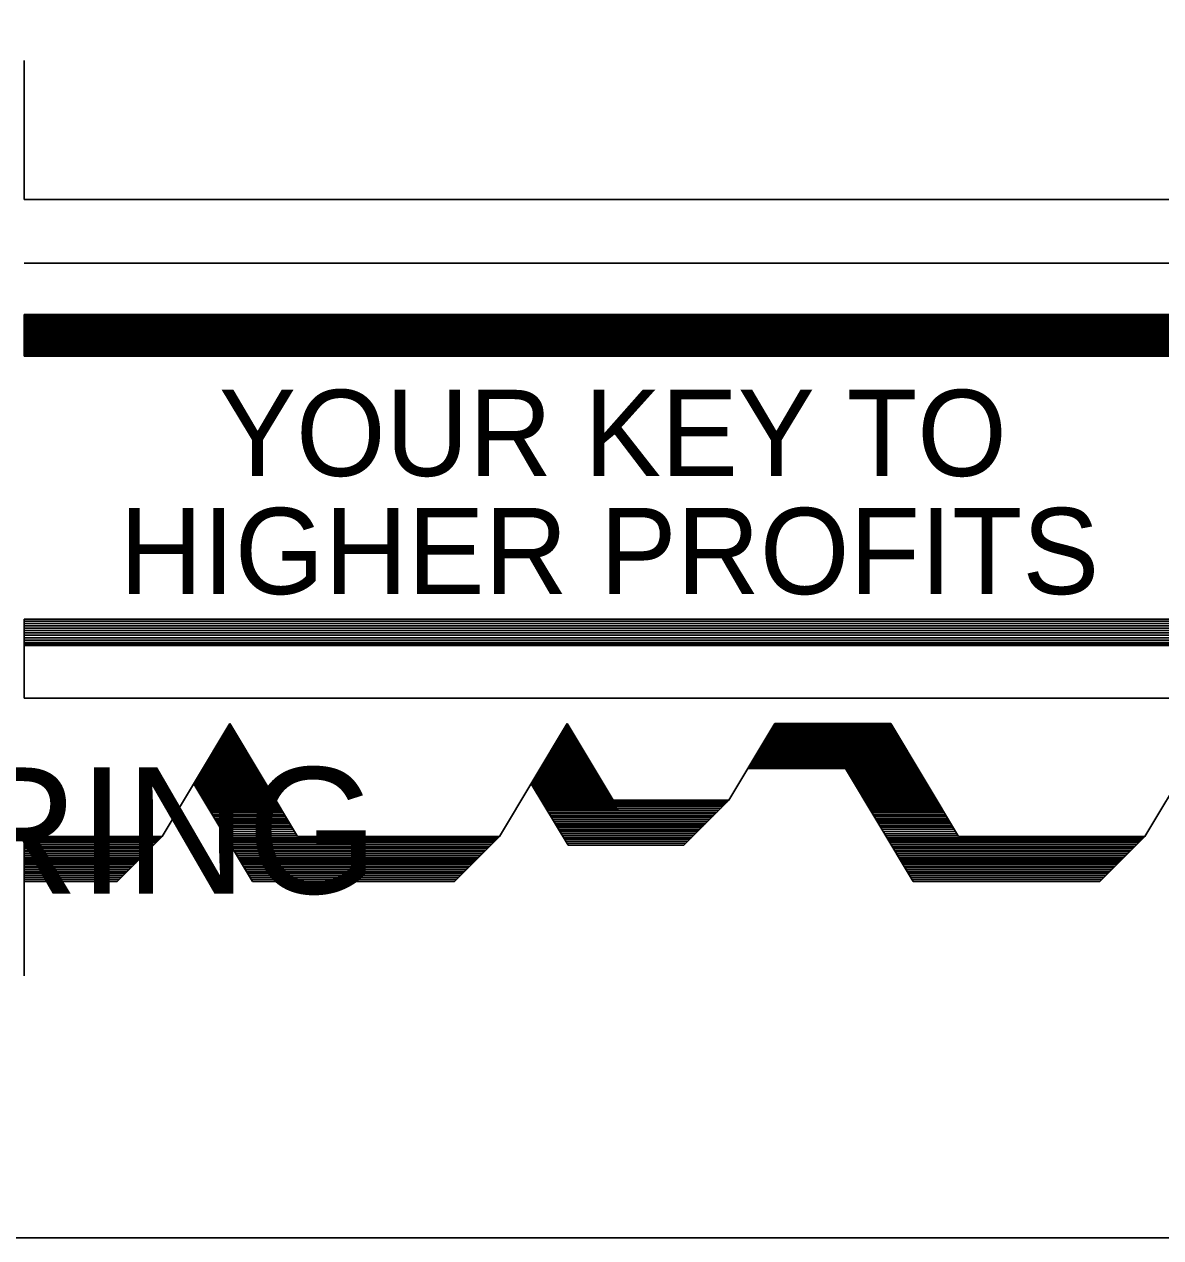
# Model space of a CAD drawing. Extents: x 22371.58 to 22374.41, y 22370.57 to 22372.4.
# Drawn here: x 22371.8644 to 22371.9387, y 22370.6319 to 22370.7113 of the extents above; entities that cross this region are included whole.
import ezdxf

# ---------------------------------------------------------------- set-up
doc = ezdxf.new("R2010")
doc.units = 0
doc.layers.add('G-ANNO-TTBL', color=7, linetype='Continuous')
doc.layers.add('S-SECT-GENF', color=7, linetype='Continuous')

msp = doc.modelspace()

# ---------------------------------------------------------------- linework, layer by layer
at = {"layer": 'G-ANNO-TTBL'}
msp.add_lwpolyline([(22371.776222, 22372.340278), (22374.192888, 22372.340278), (22374.192888, 22370.631945), (22371.776222, 22370.631945)], close=True, dxfattribs=at)
msp.add_lwpolyline([(22371.776222, 22372.340278), (22374.192888, 22372.340278), (22374.192888, 22370.631945), (22371.776222, 22370.631945)], close=True, dxfattribs=at)
at = {"layer": 'S-SECT-GENF'}
for p, q in [((22371.864367, 22370.699874), (22371.864367, 22370.708988)), ((22371.94945, 22370.699874), (22371.864367, 22370.699874)), ((22371.954492, 22370.695707), (22371.864367, 22370.695707)), ((22371.864367, 22370.689634), (22371.864367, 22370.692353)), ((22371.958544, 22370.692353), (22371.864367, 22370.692353)), ((22371.958627, 22370.69229), (22371.864367, 22370.69229)), ((22371.9587, 22370.692228), (22371.864367, 22370.692228)), ((22371.958784, 22370.692155), (22371.864367, 22370.692155)), ((22371.958877, 22370.692082), (22371.864367, 22370.692082)), ((22371.958961, 22370.692009), (22371.864367, 22370.692009)), ((22371.959065, 22370.691926), (22371.864367, 22370.691926)), ((22371.959148, 22370.691853), (22371.864367, 22370.691853)), ((22371.959252, 22370.69177), (22371.864367, 22370.69177)), ((22371.959357, 22370.691686), (22371.864367, 22370.691686)), ((22371.95944, 22370.691613), (22371.864367, 22370.691613)), ((22371.959534, 22370.69153), (22371.864367, 22370.69153)), ((22371.959648, 22370.691447), (22371.864367, 22370.691447)), ((22371.959732, 22370.691374), (22371.864367, 22370.691374)), ((22371.959815, 22370.691301), (22371.864367, 22370.691301)), ((22371.959919, 22370.691218), (22371.864367, 22370.691218)), ((22371.960023, 22370.691134), (22371.864367, 22370.691134)), ((22371.960117, 22370.691051), (22371.864367, 22370.691051)), ((22371.960232, 22370.690957), (22371.864367, 22370.690957)), ((22371.960325, 22370.690884), (22371.864367, 22370.690884)), ((22371.960419, 22370.690801), (22371.864367, 22370.690801)), ((22371.960534, 22370.690707), (22371.864367, 22370.690707)), ((22371.960638, 22370.690624), (22371.864367, 22370.690624)), ((22371.960711, 22370.690561), (22371.864367, 22370.690561)), ((22371.960815, 22370.690478), (22371.864367, 22370.690478)), ((22371.960909, 22370.690395), (22371.864367, 22370.690395)), ((22371.961002, 22370.690322), (22371.864367, 22370.690322)), ((22371.961086, 22370.690249), (22371.864367, 22370.690249)), ((22371.961169, 22370.690186), (22371.864367, 22370.690186)), ((22371.961284, 22370.690093), (22371.864367, 22370.690093)), ((22371.961357, 22370.69003), (22371.864367, 22370.69003)), ((22371.96144, 22370.689957), (22371.864367, 22370.689957)), ((22371.961513, 22370.689895), (22371.864367, 22370.689895)), ((22371.961596, 22370.689832), (22371.864367, 22370.689832)), ((22371.961659, 22370.68978), (22371.864367, 22370.68978)), ((22371.961732, 22370.689718), (22371.864367, 22370.689718)), ((22371.961784, 22370.689676), (22371.864367, 22370.689676)), ((22371.961836, 22370.689634), (22371.864367, 22370.689634)), ((22371.966659, 22370.672426), (22371.864367, 22370.672426)), ((22371.864367, 22370.667259), (22371.864367, 22370.672426)), ((22371.966492, 22370.67229), (22371.864367, 22370.67229)), ((22371.966315, 22370.672145), (22371.864367, 22370.672145)), ((22371.966117, 22370.671978), (22371.864367, 22370.671978)), ((22371.96595, 22370.671843), (22371.864367, 22370.671843)), ((22371.965752, 22370.671676), (22371.864367, 22370.671676)), ((22371.965575, 22370.67153), (22371.864367, 22370.67153)), ((22371.965388, 22370.671374), (22371.864367, 22370.671374)), ((22371.96518, 22370.671207), (22371.864367, 22370.671207)), ((22371.964992, 22370.671051), (22371.864367, 22370.671051)), ((22371.964815, 22370.670905), (22371.864367, 22370.670905)), ((22371.96469, 22370.670801), (22371.864367, 22370.670801)), ((22371.964575, 22370.670707), (22371.864367, 22370.670707)), ((22371.960409, 22370.667259), (22371.864367, 22370.667259)), ((22371.873398, 22370.658207), (22371.877825, 22370.665593)), ((22371.877711, 22370.665405), (22371.87794, 22370.665405)), ((22371.877763, 22370.665488), (22371.877888, 22370.665488)), ((22371.877825, 22370.665593), (22371.882242, 22370.658207)), ((22371.895471, 22370.658207), (22371.899888, 22370.665593)), ((22371.899763, 22370.665384), (22371.900013, 22370.665384)), ((22371.899805, 22370.665447), (22371.899971, 22370.665447)), ((22371.899836, 22370.665509), (22371.89994, 22370.665509)), ((22371.899888, 22370.665593), (22371.902898, 22370.660582)), ((22371.910482, 22370.660582), (22371.913482, 22370.665593)), ((22371.913357, 22370.665384), (22371.92119, 22370.665384)), ((22371.913398, 22370.665457), (22371.921148, 22370.665457)), ((22371.91344, 22370.66552), (22371.921107, 22370.66552)), ((22371.913482, 22370.665593), (22371.921065, 22370.665593)), ((22371.921065, 22370.665593), (22371.925492, 22370.658207)), ((22371.9377, 22370.658207), (22371.942127, 22370.665593)), ((22371.877211, 22370.664572), (22371.87844, 22370.664572)), ((22371.877263, 22370.664655), (22371.878388, 22370.664655)), ((22371.877315, 22370.664738), (22371.878336, 22370.664738)), ((22371.877367, 22370.664822), (22371.878284, 22370.664822)), ((22371.877409, 22370.664905), (22371.878232, 22370.664905)), ((22371.877461, 22370.664988), (22371.87819, 22370.664988)), ((22371.877513, 22370.665072), (22371.878138, 22370.665072)), ((22371.877565, 22370.665155), (22371.878086, 22370.665155)), ((22371.877617, 22370.665238), (22371.878034, 22370.665238)), ((22371.877659, 22370.665322), (22371.877992, 22370.665322)), ((22371.899273, 22370.664572), (22371.900502, 22370.664572)), ((22371.899325, 22370.664655), (22371.90045, 22370.664655)), ((22371.899377, 22370.664738), (22371.900398, 22370.664738)), ((22371.89943, 22370.664822), (22371.900346, 22370.664822)), ((22371.899471, 22370.664905), (22371.900294, 22370.664905)), ((22371.899523, 22370.664988), (22371.900252, 22370.664988)), ((22371.899575, 22370.665072), (22371.9002, 22370.665072)), ((22371.899627, 22370.665155), (22371.900148, 22370.665155)), ((22371.89968, 22370.665238), (22371.900096, 22370.665238)), ((22371.899721, 22370.665322), (22371.900055, 22370.665322)), ((22371.912867, 22370.664572), (22371.92168, 22370.664572)), ((22371.912919, 22370.664655), (22371.921627, 22370.664655)), ((22371.912971, 22370.664738), (22371.921575, 22370.664738)), ((22371.913023, 22370.664822), (22371.921523, 22370.664822)), ((22371.913065, 22370.664905), (22371.921471, 22370.664905)), ((22371.913117, 22370.664988), (22371.92143, 22370.664988)), ((22371.913169, 22370.665072), (22371.921377, 22370.665072)), ((22371.913221, 22370.665155), (22371.921325, 22370.665155)), ((22371.913273, 22370.665238), (22371.921273, 22370.665238)), ((22371.913315, 22370.665311), (22371.921232, 22370.665311)), ((22371.876763, 22370.663822), (22371.878888, 22370.663822)), ((22371.876815, 22370.663905), (22371.878836, 22370.663905)), ((22371.876867, 22370.663988), (22371.878784, 22370.663988)), ((22371.876919, 22370.664072), (22371.878732, 22370.664072)), ((22371.876971, 22370.664155), (22371.87869, 22370.664155)), ((22371.877023, 22370.664238), (22371.878638, 22370.664238)), ((22371.877075, 22370.664322), (22371.878586, 22370.664322)), ((22371.877127, 22370.664405), (22371.878534, 22370.664405)), ((22371.877159, 22370.664488), (22371.878482, 22370.664488)), ((22371.898825, 22370.663822), (22371.90095, 22370.663822)), ((22371.898877, 22370.663905), (22371.900898, 22370.663905)), ((22371.89893, 22370.663988), (22371.900846, 22370.663988)), ((22371.898982, 22370.664072), (22371.900794, 22370.664072)), ((22371.899034, 22370.664155), (22371.900752, 22370.664155)), ((22371.899086, 22370.664238), (22371.9007, 22370.664238)), ((22371.899138, 22370.664322), (22371.900648, 22370.664322)), ((22371.89919, 22370.664405), (22371.900596, 22370.664405)), ((22371.899221, 22370.664488), (22371.900544, 22370.664488)), ((22371.912419, 22370.663822), (22371.922127, 22370.663822)), ((22371.912471, 22370.663905), (22371.922075, 22370.663905)), ((22371.912523, 22370.663988), (22371.922023, 22370.663988)), ((22371.912575, 22370.664072), (22371.921971, 22370.664072)), ((22371.912617, 22370.664155), (22371.92193, 22370.664155)), ((22371.912669, 22370.664238), (22371.921877, 22370.664238)), ((22371.912721, 22370.664322), (22371.921825, 22370.664322)), ((22371.912773, 22370.664405), (22371.921773, 22370.664405)), ((22371.912825, 22370.664488), (22371.921721, 22370.664488)), ((22371.876284, 22370.662988), (22371.879388, 22370.662988)), ((22371.876315, 22370.663072), (22371.879336, 22370.663072)), ((22371.876367, 22370.663155), (22371.879284, 22370.663155)), ((22371.876419, 22370.663238), (22371.879232, 22370.663238)), ((22371.876461, 22370.663322), (22371.87918, 22370.663322)), ((22371.876513, 22370.663405), (22371.879138, 22370.663405)), ((22371.876565, 22370.663488), (22371.879086, 22370.663488)), ((22371.876617, 22370.663572), (22371.879034, 22370.663572)), ((22371.876669, 22370.663655), (22371.878982, 22370.663655)), ((22371.876711, 22370.663738), (22371.87893, 22370.663738)), ((22371.898346, 22370.662988), (22371.90145, 22370.662988)), ((22371.898377, 22370.663072), (22371.901398, 22370.663072)), ((22371.89843, 22370.663155), (22371.901346, 22370.663155)), ((22371.898482, 22370.663238), (22371.901294, 22370.663238)), ((22371.898523, 22370.663322), (22371.901242, 22370.663322)), ((22371.898575, 22370.663405), (22371.9012, 22370.663405)), ((22371.898627, 22370.663488), (22371.901148, 22370.663488)), ((22371.89868, 22370.663572), (22371.901096, 22370.663572)), ((22371.898732, 22370.663655), (22371.901044, 22370.663655)), ((22371.898773, 22370.663738), (22371.900992, 22370.663738)), ((22371.911919, 22370.662988), (22371.922627, 22370.662988)), ((22371.911971, 22370.663072), (22371.922575, 22370.663072)), ((22371.912023, 22370.663155), (22371.922523, 22370.663155)), ((22371.912075, 22370.663238), (22371.922471, 22370.663238)), ((22371.912117, 22370.663322), (22371.922419, 22370.663322)), ((22371.912169, 22370.663405), (22371.922377, 22370.663405)), ((22371.912221, 22370.663488), (22371.922325, 22370.663488)), ((22371.912273, 22370.663572), (22371.922273, 22370.663572)), ((22371.912325, 22370.663655), (22371.922221, 22370.663655)), ((22371.912367, 22370.663738), (22371.922169, 22370.663738)), ((22371.875763, 22370.662155), (22371.879877, 22370.662155)), ((22371.875815, 22370.662238), (22371.879836, 22370.662238)), ((22371.875867, 22370.662322), (22371.879784, 22370.662322)), ((22371.875919, 22370.662405), (22371.879732, 22370.662405)), ((22371.875971, 22370.662488), (22371.87968, 22370.662488)), ((22371.876023, 22370.662572), (22371.879627, 22370.662572)), ((22371.876075, 22370.662655), (22371.879586, 22370.662655)), ((22371.876127, 22370.662738), (22371.879534, 22370.662738)), ((22371.87618, 22370.662822), (22371.879482, 22370.662822)), ((22371.876232, 22370.662905), (22371.87943, 22370.662905)), ((22371.897825, 22370.662155), (22371.90194, 22370.662155)), ((22371.897877, 22370.662238), (22371.901898, 22370.662238)), ((22371.89793, 22370.662322), (22371.901846, 22370.662322)), ((22371.897982, 22370.662405), (22371.901794, 22370.662405)), ((22371.898034, 22370.662488), (22371.901742, 22370.662488)), ((22371.898086, 22370.662572), (22371.90169, 22370.662572)), ((22371.898138, 22370.662655), (22371.901648, 22370.662655)), ((22371.89819, 22370.662738), (22371.901596, 22370.662738)), ((22371.898242, 22370.662822), (22371.901544, 22370.662822)), ((22371.898294, 22370.662905), (22371.901492, 22370.662905)), ((22371.911721, 22370.662655), (22371.922825, 22370.662655)), ((22371.911721, 22370.662645), (22371.918117, 22370.662645)), ((22371.911773, 22370.662738), (22371.922773, 22370.662738)), ((22371.911825, 22370.662822), (22371.922721, 22370.662822)), ((22371.911877, 22370.662905), (22371.922669, 22370.662905)), ((22371.918117, 22370.662645), (22371.922544, 22370.655259)), ((22371.918159, 22370.662572), (22371.922867, 22370.662572)), ((22371.918211, 22370.662488), (22371.922919, 22370.662488)), ((22371.918263, 22370.662405), (22371.922971, 22370.662405)), ((22371.918315, 22370.662322), (22371.923023, 22370.662322)), ((22371.918357, 22370.662238), (22371.923075, 22370.662238)), ((22371.918409, 22370.662155), (22371.923117, 22370.662155)), ((22371.875471, 22370.661655), (22371.879294, 22370.655259)), ((22371.875471, 22370.661655), (22371.88018, 22370.661655)), ((22371.875513, 22370.661738), (22371.880127, 22370.661738)), ((22371.875523, 22370.661572), (22371.880232, 22370.661572)), ((22371.875565, 22370.661822), (22371.880075, 22370.661822)), ((22371.875575, 22370.661488), (22371.880284, 22370.661488)), ((22371.875617, 22370.661905), (22371.880034, 22370.661905)), ((22371.875617, 22370.661405), (22371.880325, 22370.661405)), ((22371.875669, 22370.661988), (22371.879982, 22370.661988)), ((22371.875711, 22370.662072), (22371.87993, 22370.662072)), ((22371.897534, 22370.661655), (22371.89995, 22370.657634)), ((22371.897534, 22370.661655), (22371.902242, 22370.661655)), ((22371.897575, 22370.661738), (22371.90219, 22370.661738)), ((22371.897586, 22370.661572), (22371.902294, 22370.661572)), ((22371.897627, 22370.661822), (22371.902138, 22370.661822)), ((22371.897638, 22370.661488), (22371.902346, 22370.661488)), ((22371.89768, 22370.661905), (22371.902096, 22370.661905)), ((22371.89768, 22370.661405), (22371.902388, 22370.661405)), ((22371.897732, 22370.661988), (22371.902044, 22370.661988)), ((22371.897773, 22370.662072), (22371.901992, 22370.662072)), ((22371.918461, 22370.662072), (22371.923169, 22370.662072)), ((22371.918513, 22370.661988), (22371.923221, 22370.661988)), ((22371.918565, 22370.661905), (22371.923273, 22370.661905)), ((22371.918607, 22370.661822), (22371.923315, 22370.661822)), ((22371.918659, 22370.661738), (22371.923367, 22370.661738)), ((22371.918711, 22370.661655), (22371.923419, 22370.661655)), ((22371.918763, 22370.661572), (22371.923471, 22370.661572)), ((22371.918815, 22370.661488), (22371.923523, 22370.661488)), ((22371.918857, 22370.661405), (22371.923565, 22370.661405)), ((22371.875669, 22370.661322), (22371.880377, 22370.661322)), ((22371.875721, 22370.661238), (22371.880409, 22370.661238)), ((22371.875773, 22370.661155), (22371.880461, 22370.661155)), ((22371.875815, 22370.661072), (22371.880513, 22370.661072)), ((22371.875867, 22370.660988), (22371.880565, 22370.660988)), ((22371.875919, 22370.660905), (22371.880617, 22370.660905)), ((22371.875971, 22370.660822), (22371.880669, 22370.660822)), ((22371.876023, 22370.660738), (22371.880721, 22370.660738)), ((22371.876065, 22370.660655), (22371.880773, 22370.660655)), ((22371.876117, 22370.660572), (22371.880825, 22370.660572)), ((22371.897732, 22370.661322), (22371.90244, 22370.661322)), ((22371.897784, 22370.661238), (22371.902471, 22370.661238)), ((22371.897836, 22370.661155), (22371.902523, 22370.661155)), ((22371.897877, 22370.661072), (22371.902575, 22370.661072)), ((22371.89793, 22370.660988), (22371.902627, 22370.660988)), ((22371.897982, 22370.660905), (22371.90268, 22370.660905)), ((22371.898034, 22370.660822), (22371.902732, 22370.660822)), ((22371.898086, 22370.660738), (22371.902784, 22370.660738)), ((22371.898127, 22370.660655), (22371.902836, 22370.660655)), ((22371.89818, 22370.660572), (22371.902888, 22370.660572)), ((22371.902898, 22370.660582), (22371.910482, 22370.660582)), ((22371.907534, 22370.657634), (22371.910482, 22370.660582)), ((22371.918909, 22370.661322), (22371.923617, 22370.661322)), ((22371.918961, 22370.661238), (22371.923648, 22370.661238)), ((22371.919013, 22370.661155), (22371.9237, 22370.661155)), ((22371.919055, 22370.661072), (22371.923752, 22370.661072)), ((22371.919107, 22370.660988), (22371.923805, 22370.660988)), ((22371.919159, 22370.660905), (22371.923857, 22370.660905)), ((22371.919211, 22370.660822), (22371.923909, 22370.660822)), ((22371.919263, 22370.660738), (22371.923961, 22370.660738)), ((22371.919305, 22370.660655), (22371.924013, 22370.660655)), ((22371.919357, 22370.660572), (22371.924065, 22370.660572)), ((22371.876169, 22370.660488), (22371.880877, 22370.660488)), ((22371.876211, 22370.660426), (22371.880919, 22370.660426)), ((22371.876252, 22370.660343), (22371.880961, 22370.660343)), ((22371.876305, 22370.660259), (22371.881013, 22370.660259)), ((22371.876357, 22370.660165), (22371.881075, 22370.660165)), ((22371.876419, 22370.660061), (22371.881138, 22370.660061)), ((22371.876482, 22370.659968), (22371.88119, 22370.659968)), ((22371.876544, 22370.659853), (22371.881263, 22370.659853)), ((22371.898232, 22370.660488), (22371.90294, 22370.660488)), ((22371.898273, 22370.660426), (22371.902982, 22370.660426)), ((22371.898315, 22370.660343), (22371.903023, 22370.660343)), ((22371.898367, 22370.660259), (22371.903075, 22370.660259)), ((22371.898419, 22370.660165), (22371.903138, 22370.660165)), ((22371.898482, 22370.660061), (22371.9032, 22370.660061)), ((22371.898544, 22370.659968), (22371.903252, 22370.659968)), ((22371.898575, 22370.659926), (22371.909825, 22370.659926)), ((22371.898648, 22370.659801), (22371.9097, 22370.659801)), ((22371.90145, 22370.660478), (22371.910377, 22370.660478)), ((22371.90145, 22370.660384), (22371.910284, 22370.660384)), ((22371.90145, 22370.66029), (22371.91019, 22370.66029)), ((22371.90145, 22370.660176), (22371.910075, 22370.660176)), ((22371.90145, 22370.660061), (22371.909961, 22370.660061)), ((22371.919409, 22370.660488), (22371.924117, 22370.660488)), ((22371.91945, 22370.660426), (22371.924159, 22370.660426)), ((22371.919492, 22370.660343), (22371.9242, 22370.660343)), ((22371.919544, 22370.660259), (22371.924252, 22370.660259)), ((22371.919596, 22370.660165), (22371.924315, 22370.660165)), ((22371.919659, 22370.660061), (22371.924377, 22370.660061)), ((22371.919721, 22370.659968), (22371.92443, 22370.659968)), ((22371.919784, 22370.659853), (22371.924502, 22370.659853)), ((22371.876607, 22370.659749), (22371.881315, 22370.659749)), ((22371.87669, 22370.659624), (22371.881398, 22370.659624)), ((22371.876752, 22370.659509), (22371.881461, 22370.659509)), ((22371.876825, 22370.659384), (22371.881534, 22370.659384)), ((22371.876898, 22370.659259), (22371.881617, 22370.659259)), ((22371.876961, 22370.659155), (22371.88168, 22370.659155)), ((22371.877023, 22370.659051), (22371.881742, 22370.659051)), ((22371.898721, 22370.659676), (22371.909575, 22370.659676)), ((22371.898794, 22370.659561), (22371.909461, 22370.659561)), ((22371.898867, 22370.659436), (22371.909336, 22370.659436)), ((22371.89894, 22370.659311), (22371.909211, 22370.659311)), ((22371.899013, 22370.659186), (22371.909086, 22370.659186)), ((22371.899096, 22370.659061), (22371.908961, 22370.659061)), ((22371.919846, 22370.659749), (22371.924555, 22370.659749)), ((22371.91993, 22370.659624), (22371.924638, 22370.659624)), ((22371.919992, 22370.659509), (22371.9247, 22370.659509)), ((22371.920065, 22370.659384), (22371.924773, 22370.659384)), ((22371.920138, 22370.659259), (22371.924857, 22370.659259)), ((22371.9202, 22370.659155), (22371.924919, 22370.659155)), ((22371.920263, 22370.659051), (22371.924982, 22370.659051)), ((22371.864367, 22370.649093), (22371.864367, 22370.658207)), ((22371.864367, 22370.658207), (22371.873398, 22370.658207)), ((22371.87045, 22370.655259), (22371.873398, 22370.658207)), ((22371.877107, 22370.658926), (22371.881815, 22370.658926)), ((22371.877169, 22370.658811), (22371.881877, 22370.658811)), ((22371.877242, 22370.658686), (22371.88195, 22370.658686)), ((22371.877346, 22370.65852), (22371.882055, 22370.65852)), ((22371.87743, 22370.658384), (22371.882138, 22370.658384)), ((22371.877513, 22370.658238), (22371.882221, 22370.658238)), ((22371.882242, 22370.658207), (22371.895471, 22370.658207)), ((22371.892523, 22370.655259), (22371.895471, 22370.658207)), ((22371.899138, 22370.658978), (22371.908877, 22370.658978)), ((22371.8992, 22370.658884), (22371.908784, 22370.658884)), ((22371.899273, 22370.658759), (22371.908659, 22370.658759)), ((22371.899346, 22370.658634), (22371.908534, 22370.658634)), ((22371.899409, 22370.65853), (22371.90843, 22370.65853)), ((22371.899492, 22370.658395), (22371.908294, 22370.658395)), ((22371.899565, 22370.65827), (22371.908169, 22370.65827)), ((22371.920346, 22370.658926), (22371.925055, 22370.658926)), ((22371.920409, 22370.658811), (22371.925117, 22370.658811)), ((22371.920482, 22370.658686), (22371.92519, 22370.658686)), ((22371.920586, 22370.65852), (22371.925294, 22370.65852)), ((22371.920669, 22370.658384), (22371.925377, 22370.658384)), ((22371.920752, 22370.658238), (22371.925461, 22370.658238)), ((22371.925492, 22370.658207), (22371.9377, 22370.658207)), ((22371.934752, 22370.655259), (22371.9377, 22370.658207)), ((22371.864367, 22370.658103), (22371.873294, 22370.658103)), ((22371.864367, 22370.658009), (22371.8732, 22370.658009)), ((22371.864367, 22370.657915), (22371.873107, 22370.657915)), ((22371.864367, 22370.657801), (22371.872992, 22370.657801)), ((22371.864367, 22370.657686), (22371.872877, 22370.657686)), ((22371.864367, 22370.657551), (22371.872742, 22370.657551)), ((22371.864367, 22370.657426), (22371.872617, 22370.657426)), ((22371.877596, 22370.658103), (22371.895367, 22370.658103)), ((22371.877648, 22370.658009), (22371.895273, 22370.658009)), ((22371.877711, 22370.657915), (22371.89518, 22370.657915)), ((22371.877773, 22370.657801), (22371.895065, 22370.657801)), ((22371.877846, 22370.657686), (22371.89495, 22370.657686)), ((22371.87793, 22370.657551), (22371.894815, 22370.657551)), ((22371.878002, 22370.657426), (22371.89469, 22370.657426)), ((22371.899648, 22370.658145), (22371.908044, 22370.658145)), ((22371.899711, 22370.65803), (22371.90793, 22370.65803)), ((22371.899805, 22370.657884), (22371.907784, 22370.657884)), ((22371.899877, 22370.657759), (22371.907659, 22370.657759)), ((22371.89995, 22370.657634), (22371.907534, 22370.657634)), ((22371.920836, 22370.658103), (22371.937596, 22370.658103)), ((22371.920888, 22370.658009), (22371.937502, 22370.658009)), ((22371.92095, 22370.657915), (22371.937409, 22370.657915)), ((22371.921013, 22370.657801), (22371.937294, 22370.657801)), ((22371.921086, 22370.657686), (22371.93718, 22370.657686)), ((22371.921169, 22370.657551), (22371.937044, 22370.657551)), ((22371.921242, 22370.657426), (22371.936919, 22370.657426)), ((22371.864367, 22370.657301), (22371.872492, 22370.657301)), ((22371.864367, 22370.657186), (22371.872377, 22370.657186)), ((22371.864367, 22370.657061), (22371.872252, 22370.657061)), ((22371.864367, 22370.656936), (22371.872127, 22370.656936)), ((22371.864367, 22370.656811), (22371.872002, 22370.656811)), ((22371.864367, 22370.656686), (22371.871877, 22370.656686)), ((22371.864367, 22370.656603), (22371.871794, 22370.656603)), ((22371.878075, 22370.657301), (22371.894565, 22370.657301)), ((22371.878138, 22370.657186), (22371.89445, 22370.657186)), ((22371.878221, 22370.657061), (22371.894325, 22370.657061)), ((22371.878294, 22370.656936), (22371.8942, 22370.656936)), ((22371.878367, 22370.656811), (22371.894075, 22370.656811)), ((22371.87844, 22370.656686), (22371.89395, 22370.656686)), ((22371.878492, 22370.656603), (22371.893867, 22370.656603)), ((22371.921315, 22370.657301), (22371.936794, 22370.657301)), ((22371.921377, 22370.657186), (22371.93668, 22370.657186)), ((22371.921461, 22370.657061), (22371.936555, 22370.657061)), ((22371.921534, 22370.656936), (22371.93643, 22370.656936)), ((22371.921607, 22370.656811), (22371.936305, 22370.656811)), ((22371.92168, 22370.656686), (22371.93618, 22370.656686)), ((22371.921732, 22370.656603), (22371.936096, 22370.656603)), ((22371.864367, 22370.656509), (22371.8717, 22370.656509)), ((22371.864367, 22370.656384), (22371.871575, 22370.656384)), ((22371.864367, 22370.656259), (22371.87145, 22370.656259)), ((22371.864367, 22370.656155), (22371.871346, 22370.656155)), ((22371.864367, 22370.65602), (22371.871211, 22370.65602)), ((22371.864367, 22370.655895), (22371.871086, 22370.655895)), ((22371.878544, 22370.656509), (22371.893773, 22370.656509)), ((22371.878617, 22370.656384), (22371.893648, 22370.656384)), ((22371.8787, 22370.656259), (22371.893523, 22370.656259)), ((22371.878763, 22370.656155), (22371.893419, 22370.656155)), ((22371.878836, 22370.65602), (22371.893284, 22370.65602)), ((22371.878919, 22370.655895), (22371.893159, 22370.655895)), ((22371.921784, 22370.656509), (22371.936002, 22370.656509)), ((22371.921857, 22370.656384), (22371.935877, 22370.656384)), ((22371.92194, 22370.656259), (22371.935752, 22370.656259)), ((22371.922002, 22370.656155), (22371.935648, 22370.656155)), ((22371.922075, 22370.65602), (22371.935513, 22370.65602)), ((22371.922159, 22370.655895), (22371.935388, 22370.655895)), ((22371.864367, 22370.65577), (22371.870961, 22370.65577)), ((22371.864367, 22370.655655), (22371.870846, 22370.655655)), ((22371.864367, 22370.655509), (22371.8707, 22370.655509)), ((22371.864367, 22370.655384), (22371.870575, 22370.655384)), ((22371.864367, 22370.655259), (22371.87045, 22370.655259)), ((22371.878992, 22370.65577), (22371.893034, 22370.65577)), ((22371.879055, 22370.655655), (22371.892919, 22370.655655)), ((22371.879148, 22370.655509), (22371.892773, 22370.655509)), ((22371.879221, 22370.655384), (22371.892648, 22370.655384)), ((22371.879294, 22370.655259), (22371.892523, 22370.655259)), ((22371.922232, 22370.65577), (22371.935263, 22370.65577)), ((22371.922294, 22370.655655), (22371.935148, 22370.655655)), ((22371.922388, 22370.655509), (22371.935002, 22370.655509)), ((22371.922461, 22370.655384), (22371.934877, 22370.655384)), ((22371.922544, 22370.655259), (22371.934752, 22370.655259))]:
    msp.add_line(p, q, dxfattribs=at)

# ---------------------------------------------------------------- texts
for s, height, p in [('YOUR KEY TO', 0.00564056, (22371.877117, 22370.68179)), ('HIGHER PROFITS', 0.00564056, (22371.870596, 22370.674061)), ('ENGINEERING', 0.00824938, (22371.810294, 22370.654468))]:
    msp.add_text(s, height=height, dxfattribs=at).set_placement(p)

doc.saveas('drawing.dxf')
